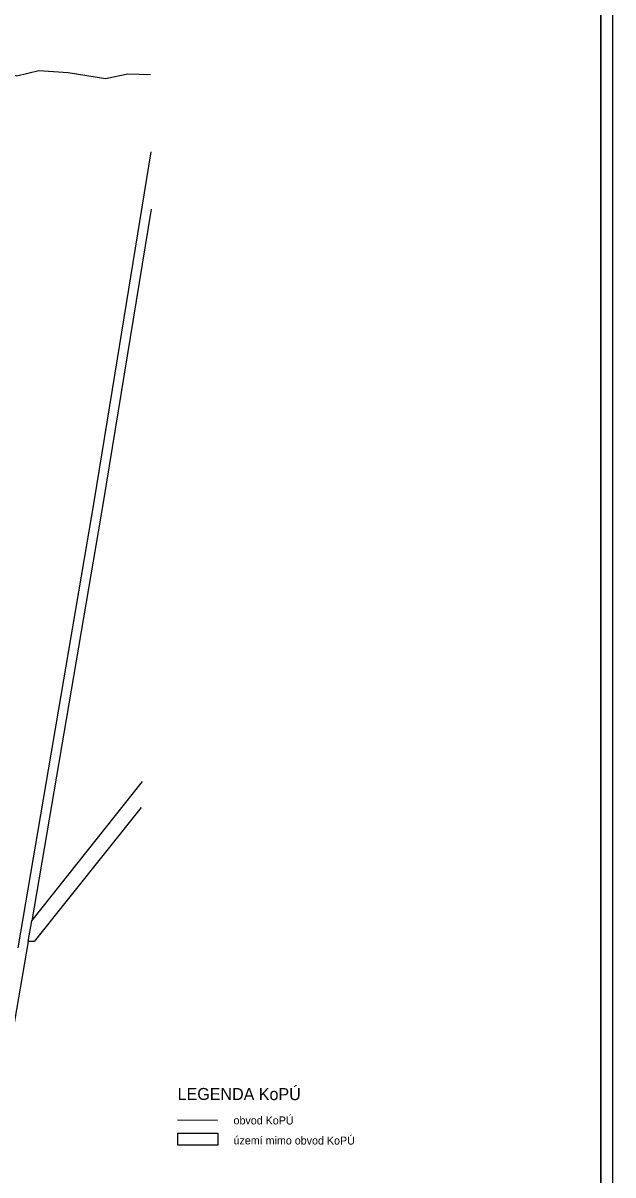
# Model space of a CAD drawing. Extents: x -555757 to -553364, y -1100723 to -1096439.
# Drawn here: x -553659 to -553364, y -1098755 to -1098179 of the extents above; entities that cross this region are included whole.
import ezdxf

# ---------------------------------------------------------------- set-up
doc = ezdxf.new("R2010")
doc.units = 0
for name, color, linetype in [('HRANICE$PARCELY', 7, 'Continuous'), ('HRANICE_PARCEL', 7, 'Continuous'), ('ram', 7, 'Continuous')]:
    doc.layers.add(name, color=color, linetype=linetype)

msp = doc.modelspace()

# ---------------------------------------------------------------- linework, layer by layer
at = {"layer": 'HRANICE$PARCELY'}
for p, q in [((-553654.64, -1098628.16), (-553599.28, -1098558.55)), ((-553656.41, -1098638.56), (-553654.64, -1098628.16))]:
    msp.add_line(p, q, dxfattribs=at)
for points in [[(-553595.18, -1098243.75), (-553613.13, -1098354.33), (-553623.73, -1098418.67), (-553661.65, -1098641.68)], [(-553595.03, -1098272.34), (-553619.04, -1098418.98), (-553654.64, -1098628.16)], [(-553600.02, -1098571.6), (-553653.5, -1098638.46), (-553656.41, -1098638.56)], [(-553656.41, -1098638.56), (-553665.29, -1098690.06), (-553676.92, -1098757.5)]]:
    msp.add_lwpolyline(points, dxfattribs=at)
at = {"layer": 'HRANICE_PARCEL'}
for points in [[(-553678.8, -1098200.76), (-553662.21, -1098205.7), (-553651.07, -1098203.11), (-553636.4, -1098204.01), (-553617.78, -1098207.06)], [(-553617.78, -1098207.06), (-553606.69, -1098204.73), (-553595.38, -1098205.04)]]:
    msp.add_lwpolyline(points, dxfattribs=at)
at = {"layer": 'ram'}
msp.add_line((-553561.84, -1098727.95), (-553581.84, -1098727.91), dxfattribs=at)
for points in [[(-554624.2, -1099020.57), (-553364.2, -1099020.57), (-553364.2, -1096520.57), (-554624.2, -1096520.57), (-554624.2, -1099020.57)], [(-554624.2, -1099020.57), (-553364.2, -1099020.57), (-553364.2, -1096520.57), (-554624.2, -1096520.57), (-554624.2, -1099020.57)], [(-554618.2, -1096526.57), (-553370.2, -1096526.57), (-553370.2, -1099014.57), (-554618.2, -1099014.57), (-554618.2, -1096526.57)], [(-553581.75, -1098740.31), (-553581.75, -1098734.31), (-553561.75, -1098734.31), (-553561.75, -1098740.31), (-553581.75, -1098740.31)]]:
    msp.add_lwpolyline(points, dxfattribs=at)
msp.add_lwpolyline([(-554618.2, -1099014.57), (-553370.2, -1099014.57), (-553370.2, -1096526.57), (-554618.2, -1096526.57)], close=True, dxfattribs=at)

# ---------------------------------------------------------------- texts
for s, height, p in [('LEGENDA KoPÚ', 6, (-553581.77, -1098717.74)), ('obvod KoPÚ', 4, (-553553.84, -1098729.96)), ('území mimo obvod KoPÚ', 4, (-553553.84, -1098739.96))]:
    msp.add_text(s, height=height, rotation=359.89336, dxfattribs=at).set_placement(p)

doc.saveas('drawing.dxf')
